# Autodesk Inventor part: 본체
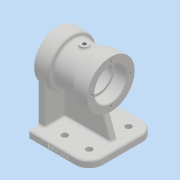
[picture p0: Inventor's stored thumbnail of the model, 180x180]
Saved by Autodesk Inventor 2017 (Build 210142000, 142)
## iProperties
Part Number: 본체
Material: 알루미늄 6061
Document SubType Name: Modeling
Designer: 222
Density: 2.7 g/cm^3
Appearance: 알루미늄 - 평지
Mass: 725.391 g
Surface Area: 641.482 cm^2
Volume: 268.663 cm^3
Author: 222
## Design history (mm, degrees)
sketch "스케치1"
  geometry: L1 (0, 49)-(90, 49); L2 (90, 49)-(90, -49); L3 (90, -49)-(0, -49); L4 (0, -49)-(0, 49); 2 further points
  constraints: 8 end point, 2 midpoint, 2 parallel, 1 horizontal, 1 horizontal alignment, 1 perpendicular
  dimensions: "d0" = 98 distance of L1.end L2.end; "d1" = 90 distance of L2.end L3.end
extrude "돌출1" new body sketch "스케치1" distance "d2" = 10; taper "d3" = 0 deg
fillet "모깎기1" dims "d4" = 20
sketch "스케치2"
  geometry: C1 r 4.5 at (70, 29); C2 r 4.5 at (34, 29); C3 r 4.5 at (34, -29); C4 r 4.5 at (70, -29); A1 r 20 centre (70, 29) between (90, 29) and (70, 49) reference; 1 further point
  constraints: 4 centre point, 2 horizontal alignment, 2 vertical alignment, 1 concentric
  dimensions: "d5" = 9 diameter of C1; "d6" = 9 diameter of C2; "d7" = 9 diameter of C3; "d8" = 9 diameter of C4; "d9" = 58 distance of C1.centre C4.centre; "d10" = 36 distance of C2.centre C1.centre
extrude "돌출2" cut sketch "스케치2" stored distance "d11" = 10; taper "d12" = 0 deg
sketch "스케치3"
  geometry: L1 (20.912, 80)-(-108.383, 80); L2 (5, 115)-(-17, 115); L3 (-17, 115)-(-17, 109); L4 (-17, 109)-(-51, 109); L5 (-51, 109)-(-51, 115); L6 (-51, 115)-(-73, 115); L7 (-73, 115)-(-73, 103.5); L8 (-73, 103.5)-(-55, 103.5); L9 (-55, 103.5)-(-55, 100); L10 (-55, 100)-(-49, 100); L11 (-49, 100)-(-49, 103); L12 (-49, 103)-(-19, 103); L13 (-19, 103)-(-19, 100); L14 (-19, 100)-(-13, 100); L15 (-13, 100)-(-13, 103.5); L16 (-13, 103.5)-(5, 103.5); L17 (5, 103.5)-(5, 115); L18 (0, 0)-(0, 10) reference
  constraints: 34 end point, 12 perpendicular, 6 point on line, 2 horizontal
  dimensions: "d13" = 80 distance from line of L1 L18.start; "d14" = 70 diameter of L6 L1; "d15" = 47 diameter of L8 L1; "d16" = 78 distance between parallel lines of L7 L17; "d17" = 22 distance of L2.start L2.end; "d18" = 22 distance of L5.end L6.end; "d19" = 18 distance of L15.end L16.end; "d20" = 6 distance of L13.end L14.end; "d21" = 30 distance of L11.end L12.end; "d22" = 18 distance of L7.end L8.end; "d23" = 46 diameter of L12 L1; "d24" = 58 diameter of L4 L1; "d25" = 40 diameter of L14 L1; "d26" = 5 distance between parallel lines of L17 L18
revolve "회전1" sketch "스케치3" stored, may be unused: angle "d27" = 90 deg
node "작업 평면1"
sketch "스케치4"
  geometry: L1 (-5, 23.5)-(-5, -23.5) reference; C1 r 6 at (34, 0); 1 further point
  constraints: 1 centre point, 1 horizontal alignment
  dimensions: "d29" = 12 diameter of C1; "d30" = 39 distance from line of L1 C1.centre
extrude "돌출3" join sketch "스케치4" stored distance "d31" = 10; taper "d32" = 0 deg
sketch "스케치6"
  geometry: L1 (10, 84)-(10, 14); L2 (10, 14)-(80, 14); L3 (80, 14)-(80, 84); L4 (80, 84)-(10, 84); L5 (0, 0)-(0, 98) reference; L6 (10, 98)-(10, 0) reference; C1 r 23.5 at (80, 49) reference; 3 further points
  constraints: 8 end point, 3 midpoint, 3 perpendicular, 1 collinear, 1 horizontal alignment, 1 vertical
  dimensions: "d34" = 70 distance between parallel lines of L4 L2
extrude "돌출4" join sketch "스케치6" distance "d35" = 10; taper "d36" = 0 deg
sketch "스케치7"
  geometry: L1 (-10, 10)-(-10, 80) reference; L2 (-10, 10)-(-78, 10); L3 (-78, 10)-(-52.522, 80); L4 (-10, 80)-(-52.522, 80); L5 (-90, 10)-(-90, 0) reference; 1 further point
  constraints: 6 end point, 2 horizontal
  dimensions: "d37" = 70 deg angle of L2 L3; "d38" = 12 distance from line of L2.end L5
extrude "돌출5" join sketch "스케치7" stored distance "d39" = 10; taper "d40" = 0 deg
hole "구멍1" diameter "d43" = 47; stored, may be unused: countersink angle "d47" = 90 deg, drill point angle "d49" = 0 deg; dims "d41" = 10, "d42" = 10, "d44" = 6, "d45" = 4, "d46" = 2, "d48" = 18
hole "구멍2" diameter "d52" = 40; stored, may be unused: countersink angle "d56" = 90 deg, drill point angle "d58" = 0 deg; dims "d50" = 10, "d51" = 10, "d53" = 6, "d54" = 4, "d55" = 2, "d57" = 6
hole "구멍3" diameter "d61" = 46; stored, may be unused: countersink angle "d65" = 90 deg, drill point angle "d67" = 0 deg; dims "d59" = 10, "d60" = 10, "d62" = 6, "d63" = 4, "d64" = 2, "d66" = 30
hole "구멍4" diameter "d70" = 40; stored, may be unused: countersink angle "d74" = 90 deg, drill point angle "d76" = 0 deg; dims "d68" = 10, "d69" = 10, "d71" = 6, "d72" = 4, "d73" = 2, "d75" = 6
sketch "스케치8" dims "d77" = 57
  geometry: C1 r 20 at (0, 0) reference; 3 further points
  constraints: 2 horizontal alignment, 1 coincident, 2 other
hole "구멍5" sketch "스케치8" at (-28.5, 0) diameter "d78" = 3.242; stored, may be unused: countersink angle "d82" = 90 deg, drill point angle "d84" = 120 deg; dims "d79" = 10, "d80" = 4, "d81" = 2, "d83" = 12
sketch "스케치9" dims "d88" = 57
  geometry: C1 r 20 at (0, 0) reference; 3 further points
  constraints: 2 horizontal alignment, 1 coincident, 2 other
hole "구멍6" sketch "스케치9" at (28.5, 0) diameter "d89" = 3.242; stored, may be unused: countersink angle "d93" = 90 deg, drill point angle "d95" = 120 deg; dims "d90" = 10, "d91" = 4, "d92" = 2, "d94" = 12
hole "구멍7" diameter "d101" = 5.188; stored, may be unused: countersink angle "d105" = 90 deg, drill point angle "d107" = 120 deg; dims "d99" = 10, "d100" = 10, "d102" = 12, "d103" = 4, "d104" = 2, "d106" = 16
hole "구멍8" diameter "d110" = 47; stored, may be unused: countersink angle "d114" = 90 deg, drill point angle "d116" = 0 deg; dims "d108" = 10, "d109" = 10, "d111" = 12, "d112" = 4, "d113" = 2, "d115" = 18
sketch "스케치10"
  geometry: L1 (0, 0)-(0, 10) reference; 1 further point
  constraints: 1 other
  dimensions: "d117" = 45 distance from line of point (45, 4) L1; "d118" = 4 vertical distance of point (45, 4) L1.start
feature "엠보싱1" sketch "스케치10" dims "d0" = 98, "d1" = 90, "d119" = 0.5, "d120" = 0
chamfer "모따기1" distance "d121" = 1; stored, may be unused: second distance "d122" = 2, angle "d123" = 45 deg
fillet "모깎기2" dims "d124" = 0.3, "d125" = 3
fillet "모깎기3" dims "d126" = 3
fillet "모깎기4" dims "d127" = 3
fillet "모깎기5" dims "d128" = 3
node "솔리드1"
pattern_circular "원형 패턴1" dims angle "d86" = 360 deg
pattern_circular "원형 패턴2" dims angle "d97" = 360 deg
other parameters: "d28" = 112
